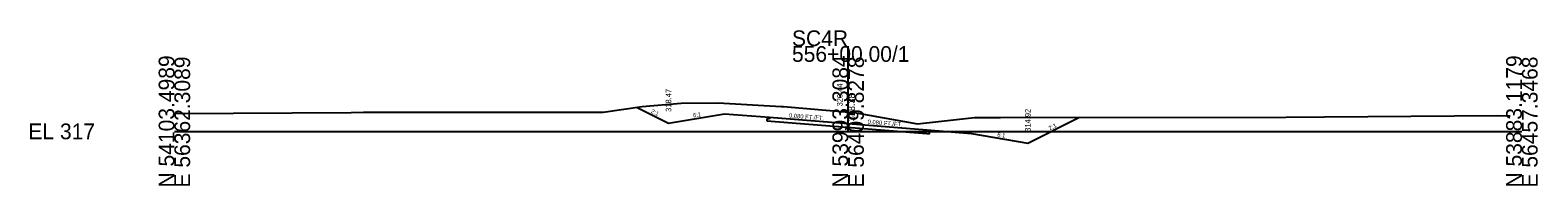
# Model space of a CAD drawing. Extents: x 9740 to 17409, y 8856 to 28416.
# Drawn here: x 12740.2 to 13008.7, y 16861.7 to 16889.4 of the extents above; entities that cross this region are included whole.
import ezdxf

# ---------------------------------------------------------------- set-up
doc = ezdxf.new("R2010")
doc.units = 0
for name, color, linetype in [('Level 10', 7, 'Continuous'), ('Level 11', 7, 'Continuous'), ('Level 12', 7, 'Continuous'), ('Level 32', 7, 'Continuous'), ('Level 33', 7, 'Continuous'), ('Level 53', 7, 'Continuous'), ('Level 59', 7, 'Continuous'), ('Level 6', 7, 'Continuous'), ('Level 60', 7, 'Continuous'), ('Level 63', 7, 'Continuous'), ('Level 7', 7, 'Continuous')]:
    doc.layers.add(name, color=color, linetype=linetype)

msp = doc.modelspace()

# ---------------------------------------------------------------- linework, layer by layer
at = {"layer": 'Level 11'}
for p, q in [((12871.85, 16873.58), (12871.35, 16873.62)), ((12871.35, 16873.62), (12871.35, 16873.28)), ((12871.85, 16873.88), (12871.85, 16873.58)), ((12899.85, 16871.34), (12899.85, 16871.64)), ((12900.35, 16871.3), (12899.85, 16871.34)), ((12899.85, 16871), (12900.35, 16870.96)), ((12900.35, 16870.96), (12900.35, 16871.3))]:
    msp.add_line(p, q, dxfattribs=at)
at = {"layer": 'Level 12'}
msp.add_line((12871.35, 16873.28), (12899.85, 16871), dxfattribs=at)
at = {"layer": 'Level 53'}
msp.add_line((12885.85, 16874.49), (12887.05, 16874.4), dxfattribs=at)
at = {"layer": 'Level 59'}
for p, q in [((12871.85, 16873.88), (12885.85, 16872.76)), ((12885.85, 16872.76), (12899.85, 16871.64))]:
    msp.add_line(p, q, dxfattribs=at)
at = {"layer": 'Level 6'}
for p, q in [((12863.85, 16874.52), (12871.85, 16873.88)), ((12899.85, 16871.64), (12907.85, 16870.97))]:
    msp.add_line(p, q, dxfattribs=at)
at = {"layer": 'Level 60'}
for p, q in [((12765.85, 16874.58), (12797.33, 16874.75)), ((12797.33, 16874.75), (12799.52, 16874.77)), ((12799.52, 16874.77), (12842.22, 16874.79)), ((12842.22, 16874.79), (12849.14, 16875.78)), ((12849.14, 16875.78), (12856.11, 16876.39)), ((12856.11, 16876.39), (12862.71, 16876.44)), ((12862.71, 16876.44), (12873.94, 16875.81)), ((12873.94, 16875.81), (12874.34, 16875.79)), ((12874.34, 16875.79), (12886.02, 16874.81)), ((12886.02, 16874.81), (12886.7, 16874.75)), ((12886.7, 16874.75), (12887.28, 16874.66)), ((12887.28, 16874.66), (12898.19, 16872.69)), ((12898.19, 16872.69), (12908.38, 16873.82)), ((12908.38, 16873.82), (12909.86, 16873.87)), ((12909.86, 16873.87), (12913, 16873.84)), ((12913, 16873.84), (12963.83, 16873.89)), ((12963.83, 16873.89), (12970.69, 16873.98)), ((12970.69, 16873.98), (13001.5, 16874.2)), ((13001.5, 16874.2), (13003.76, 16874.17))]:
    msp.add_line(p, q, dxfattribs=at)
at = {"layer": 'Level 63'}
for p, q in [((12885.85, 16871.38), (12885.85, 16886.55)), ((12765.85, 16871.38), (12885.85, 16871.38)), ((12885.85, 16871.38), (13005.85, 16871.38))]:
    msp.add_line(p, q, dxfattribs=at)
at = {"layer": 'Level 7'}
for p, q in [((12848.25, 16875.65), (12853.85, 16872.85)), ((12853.85, 16872.85), (12863.85, 16874.52)), ((12917.85, 16869.3), (12926.95, 16873.85)), ((12907.85, 16870.97), (12917.85, 16869.3))]:
    msp.add_line(p, q, dxfattribs=at)

# ---------------------------------------------------------------- texts
at = {"layer": 'Level 10'}
msp.add_text('320.44', height=1, rotation=90, dxfattribs=at).set_placement((12884.85, 16875.82))
at = {"layer": 'Level 32'}
for s, rotation, p in [('2:1', 333.435, (12850.65, 16874.73)), ('6:1', 9.4623, (12858.29, 16873.84)), ('0.080 FT./FT.', 355.4261, (12875.29, 16873.85)), ('0.080 FT./FT.', 355.4261, (12889.29, 16872.73)), ('2:1', 26.5651, (12921.78, 16871.55)), ('6:1', 350.5377, (12912.37, 16870.47))]:
    msp.add_text(s, height=0.75, rotation=rotation, dxfattribs=at).set_placement(p)
at = {"layer": 'Level 33'}
for s, p in [('318.47', (12854.35, 16874.85)), ('314.92', (12918.35, 16871.3))]:
    msp.add_text(s, height=1, rotation=90, dxfattribs=at).set_placement(p)
at = {"layer": 'Level 59'}
msp.add_text(' 318.38', height=1.2, rotation=90, dxfattribs=at).set_placement((12887.05, 16872.76))
at = {"layer": 'Level 63'}
for s, p in [('SC4R', (12875.85, 16886.55)), ('556+00.00/1', (12875.85, 16883.75)), ('EL 317', (12739.85, 16869.98))]:
    msp.add_text(s, height=2.8, dxfattribs=at).set_placement(p)
for s, p in [('N 54103.4989', (12765.85, 16861.38)), ('E 56362.3089', (12768.65, 16861.38)), ('N 53993.3084', (12885.85, 16861.38)), ('E 56409.8278', (12888.65, 16861.38)), ('N 53883.1179', (13005.85, 16861.38)), ('E 56457.3468', (13008.65, 16861.38))]:
    msp.add_text(s, height=2.8, rotation=90, dxfattribs=at).set_placement(p)

doc.saveas('drawing.dxf')
